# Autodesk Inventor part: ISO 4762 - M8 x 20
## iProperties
Comments: To add or edit properties for Autodesk Inventor files, use iProperties.
Created: 2004-07
Part Number: ISO 4762 - M8 x 20
Vendor: Autodesk Inc.
Document SubType Name: Modeling
Designer: John Blackburn
Material: Default
Description: Hexagon Socket Head Cap Screw
Standard: ISO 4762
Size Designation: M8 x 20
Alert: To add or edit properties for Autodesk Inventor files, use iProperties.
Control State: 0
Master: False
Checked Out: False
Shininess: 64.0
Length Units: 11269
Angle Units: 11279
Time Units: 11290
Mass Units: 11283
Length Display Precision: 3
Angle Display Precision: 2
Compacted: True
EGR: 1
Density: 0.0
Volumn: 0.0
Area: 0.0
PropertySet Name: Model Information
Author: John Blackburn
Revision Number: 8
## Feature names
1. Body [Revolution]
2. Slot [Extrusion]
3. Fillet1
4. Chamfer1
